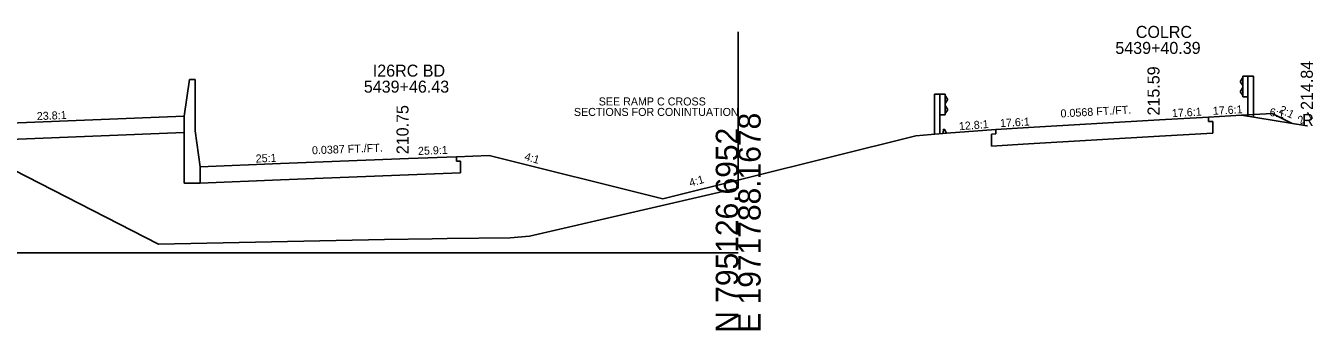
# Model space of a CAD drawing. Extents: x -161 to 1970889, y -4362 to 797231.
# Drawn here: x 1211 to 1371.8, y 5990.3 to 6028.4 of the extents above; entities that cross this region are included whole.
import ezdxf

# ---------------------------------------------------------------- set-up
doc = ezdxf.new("R2010")
doc.units = 0
for name, color, linetype in [('RD_GPK_XS_Cell', 7, 'Continuous'), ('RD_XS_Base', 7, 'Continuous'), ('RD_XS_CurbTop', 7, 'Continuous'), ('RD_XS_EarthShd', 7, 'Continuous'), ('RD_XS_ExGround', 7, 'Continuous'), ('RD_XS_GR', 7, 'Continuous'), ('RD_XS_MedBWall', 7, 'Continuous'), ('RD_XS_Pave', 7, 'Continuous'), ('RD_XS_PaveShd', 7, 'Continuous'), ('RD_XS_TieSlope', 7, 'Continuous'), ('RD_XS_TX_Elev_PR', 7, 'Continuous'), ('RD_XS_TX_Misc', 7, 'Continuous'), ('RD_XS_TX_MkPT', 7, 'Continuous'), ('RD_XS_TX_Notes', 7, 'Continuous'), ('RD_XS_TX_Profile', 7, 'Continuous'), ('RD_XS_TX_ShdSlope', 7, 'Continuous'), ('RD_XS_TX_Slope', 7, 'Continuous'), ('RD_XS_TX_Station', 7, 'Continuous')]:
    doc.layers.add(name, color=color, linetype=linetype)

msp = doc.modelspace()

# ---------------------------------------------------------------- linework, layer by layer
at = {"layer": 'RD_GPK_XS_Cell'}
msp.add_line((1150, 6000), (1300, 6000), dxfattribs=at)
at = {"layer": 'RD_XS_Base'}
for p, q in [((1358.76, 6016.38), (1358.76, 6016.94)), ((1209, 6014.13), (1230.81, 6015.04)), ((1331.66, 6014.81), (1332.17, 6014.84)), ((1332.17, 6014.84), (1332.17, 6015.4)), ((1352.63, 6014.55), (1359.27, 6014.93)), ((1359.27, 6016.41), (1358.76, 6016.38)), ((1359.27, 6014.93), (1359.27, 6016.41)), ((1331.66, 6013.33), (1331.66, 6014.81)), ((1336.27, 6013.6), (1331.66, 6013.33)), ((1336.27, 6013.6), (1352.63, 6014.55)), ((1264.82, 6011.43), (1264.82, 6011.99)), ((1232.81, 6010.17), (1232.81, 6010.73)), ((1265.32, 6011.45), (1264.82, 6011.43)), ((1265.32, 6009.97), (1265.32, 6011.45)), ((1242.82, 6009.09), (1232.81, 6008.69)), ((1242.82, 6009.09), (1258.82, 6009.71)), ((1258.82, 6009.71), (1265.32, 6009.97))]:
    msp.add_line(p, q, dxfattribs=at)
at = {"layer": 'RD_XS_CurbTop'}
for p, q in [((1325.57, 6014.89), (1325.63, 6015.32)), ((1326.03, 6014.92), (1325.57, 6014.89)), ((1326.03, 6014.92), (1325.78, 6015.38))]:
    msp.add_line(p, q, dxfattribs=at)
msp.add_ellipse((1325.71, 6015.3), major_axis=(0, 0.131), ratio=0.686, start_param=5.388101, end_param=7.661995, dxfattribs=at)
at = {"layer": 'RD_XS_EarthShd'}
for p, q in [((1358.76, 6016.94), (1362.85, 6017.17)), ((1332.17, 6015.4), (1326.03, 6014.92)), ((1268.9, 6012.15), (1264.82, 6011.99))]:
    msp.add_line(p, q, dxfattribs=at)
at = {"layer": 'RD_XS_ExGround'}
msp.add_lwpolyline([(1201.23, 6014.58), (1227.58, 6001.07), (1255.84, 6001.66), (1261.76, 6001.74), (1263.64, 6001.76), (1271.53, 6001.84), (1273.92, 6002.08), (1299.16, 6007.88), (1300, 6008.06)], dxfattribs=at)
at = {"layer": 'RD_XS_GR'}
for p, q in [((1363.02, 6021.88), (1362.75, 6021.44)), ((1362.75, 6021.44), (1362.75, 6021.33)), ((1362.75, 6021.33), (1363.02, 6020.89)), ((1363.02, 6022.04), (1363.68, 6022.04)), ((1363.02, 6019.48), (1363.02, 6022.04)), ((1363.68, 6022.04), (1364.35, 6022.04)), ((1363.68, 6022.04), (1363.68, 6017.1)), ((1364.35, 6022.04), (1364.35, 6016.99)), ((1325.2, 6019.8), (1324.54, 6019.8)), ((1324.54, 6019.8), (1324.54, 6014.75)), ((1325.87, 6019.8), (1325.2, 6019.8)), ((1325.2, 6019.8), (1325.2, 6014.86)), ((1325.87, 6017.23), (1325.87, 6019.8)), ((1362.75, 6020.19), (1363.02, 6020.63)), ((1362.75, 6020.08), (1362.75, 6020.19)), ((1363.02, 6019.64), (1362.75, 6020.08)), ((1325.87, 6019.64), (1326.14, 6019.2)), ((1326.14, 6019.09), (1325.87, 6018.65)), ((1326.14, 6017.94), (1325.87, 6018.38)), ((1326.14, 6019.2), (1326.14, 6019.09)), ((1363.02, 6019.48), (1363.68, 6019.48)), ((1325.87, 6017.23), (1325.2, 6017.23)), ((1325.87, 6017.39), (1326.14, 6017.83)), ((1326.14, 6017.83), (1326.14, 6017.94))]:
    msp.add_line(p, q, dxfattribs=at)
at = {"layer": 'RD_XS_MedBWall'}
for p, q in [((1230.81, 6017.08), (1231.48, 6021.63)), ((1232.15, 6021.63), (1231.48, 6021.63)), ((1232.15, 6021.63), (1232.15, 6015.24)), ((1230.81, 6017.08), (1230.81, 6015.04)), ((1230.81, 6017.05), (1230.81, 6008.69)), ((1232.81, 6010.73), (1232.15, 6015.24)), ((1232.81, 6010.73), (1232.81, 6008.69)), ((1232.81, 6008.69), (1230.81, 6008.69))]:
    msp.add_line(p, q, dxfattribs=at)
at = {"layer": 'RD_XS_Pave'}
for p, q in [((1336.27, 6015.64), (1352.63, 6016.59)), ((1242.82, 6011.13), (1258.82, 6011.75))]:
    msp.add_line(p, q, dxfattribs=at)
at = {"layer": 'RD_XS_PaveShd'}
for p, q in [((1209, 6016.17), (1230.81, 6017.08)), ((1352.63, 6016.59), (1358.76, 6016.94)), ((1336.27, 6015.64), (1332.17, 6015.4)), ((1258.82, 6011.75), (1264.82, 6011.99)), ((1242.82, 6011.13), (1232.81, 6010.73))]:
    msp.add_line(p, q, dxfattribs=at)
at = {"layer": 'RD_XS_TieSlope'}
for p, q in [((1362.85, 6017.17), (1366.68, 6017.39)), ((1362.85, 6017.17), (1371.03, 6015.84)), ((1366.68, 6017.39), (1369.11, 6016.2)), ((1326.03, 6014.92), (1322.2, 6014.62)), ((1371.03, 6015.84), (1371.12, 6015.88)), ((1322.2, 6014.62), (1290.59, 6006.72)), ((1268.9, 6012.15), (1290.59, 6006.72))]:
    msp.add_line(p, q, dxfattribs=at)
at = {"layer": 'RD_XS_TX_Notes'}
msp.add_line((1300, 6008.06), (1300, 6027.59), dxfattribs=at)

# ---------------------------------------------------------------- texts
at = {"layer": 'RD_GPK_XS_Cell'}
for s, p in [('E 1971788.1678', (1302.8, 5990)), ('N 795126.6952', (1300, 5990))]:
    msp.add_text(s, height=2.8, rotation=90, dxfattribs=at).set_placement(p)
at = {"layer": 'RD_XS_TX_Elev_PR'}
for s, p in [(' 215.59', (1352.63, 6016.59)), (' 210.75', (1258.82, 6011.75))]:
    msp.add_text(s, height=1.5, rotation=90, dxfattribs=at).set_placement(p)
at = {"layer": 'RD_XS_TX_Misc'}
msp.add_text('214.84', height=1.5, rotation=90, dxfattribs=at).set_placement((1371.78, 6017.84))
at = {"layer": 'RD_XS_TX_MkPT'}
msp.add_text('R', height=1.5, dxfattribs=at).set_placement((1370.44, 6015.84))
at = {"layer": 'RD_XS_TX_Notes'}
for s, p in [('SECTIONS FOR CONINTUATION', (1279.48, 6017.09)), ('SEE RAMP C CROSS ', (1282.58, 6018.4))]:
    msp.add_text(s, height=1, rotation=360, dxfattribs=at).set_placement(p)
at = {"layer": 'RD_XS_TX_Profile'}
for s, rotation, p in [('23.8:1', 2.405, (1212.41, 6016.56)), ('25.9:1', 2.2152, (1260.02, 6012.21))]:
    msp.add_text(s, height=1, rotation=rotation, dxfattribs=at).set_placement(p)
at = {"layer": 'RD_XS_TX_ShdSlope'}
for s, rotation, p in [('17.6:1', 3.2566, (1359.31, 6017.22)), ('12.8:1', 4.47, (1327.61, 6015.3))]:
    msp.add_text(s, height=1, rotation=rotation, dxfattribs=at).set_placement(p)
at = {"layer": 'RD_XS_TX_Slope'}
for s, rotation, p in [('0.0568 FT./FT.', 3.2528, (1340.29, 6016.89)), ('17.6:1', 3.2566, (1354.2, 6016.93)), ('6:1', 350.7391, (1366.32, 6017.11)), ('2:1', 333.9335, (1367.48, 6017.55)), ('17.6:1', 3.2528, (1332.73, 6015.69)), ('2:1', 26.0665, (1370.22, 6016)), ('0.0387 FT./FT.', 2.2152, (1246.78, 6012.29)), ('25:1', 2.2898, (1239.75, 6011.26)), ('4:1', 344.1175, (1273.23, 6011.6)), ('4:1', 15.8825, (1294.03, 6008.23))]:
    msp.add_text(s, height=1, rotation=rotation, dxfattribs=at).set_placement(p)
at = {"layer": 'RD_XS_TX_Station'}
for s, p in [('COLRC', (1349.67, 6026.84)), ('5439+40.39', (1347.11, 6024.84)), ('I26RC BD', (1254.36, 6022)), ('5439+46.43', (1253.24, 6020))]:
    msp.add_text(s, height=1.5, dxfattribs=at).set_placement(p)

doc.saveas('drawing.dxf')
